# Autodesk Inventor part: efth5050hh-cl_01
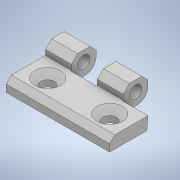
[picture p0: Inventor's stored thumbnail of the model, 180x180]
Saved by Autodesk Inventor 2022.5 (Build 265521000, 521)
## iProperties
Part Number: efth5050hh-cl_01
Material: 一般
Document SubType Name: Modeling
Designer: ImaoCorp
Density: 1 g/cm^3
Appearance: 既定
Author: ImaoCorp
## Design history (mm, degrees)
feature "efth5050hh-cl_01"
node "ソリッド1"
